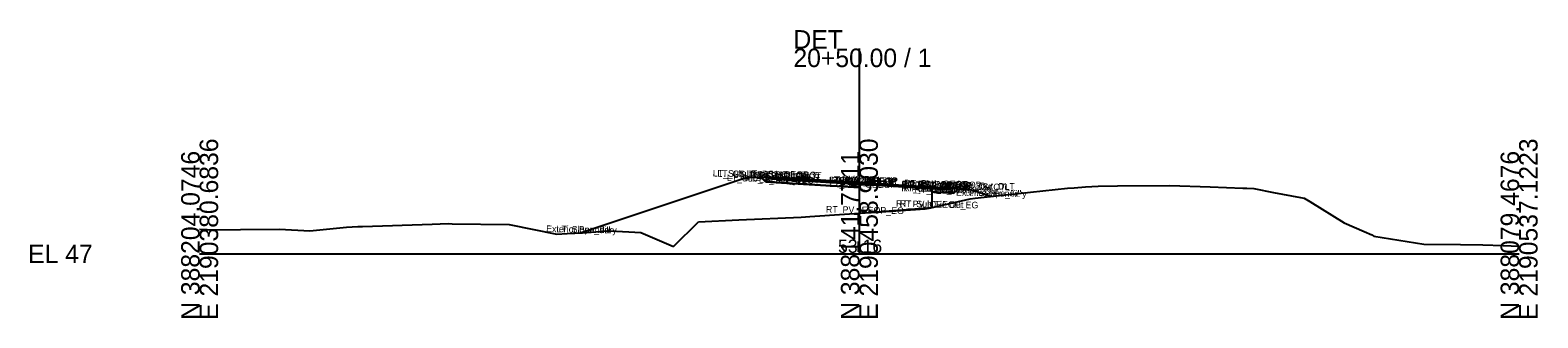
# Model space of a CAD drawing. Extents: x -26 to 1203, y -10 to 9543.
# Drawn here: x 974.3 to 1202.8, y 490.3 to 533.9 of the extents above; entities that cross this region are included whole.
import ezdxf

# ---------------------------------------------------------------- set-up
doc = ezdxf.new("R2010")
doc.units = 0
for name, color, linetype in [('Default', 7, 'Continuous'), ('Exist CMT Pavement', 7, 'Continuous'), ('Exist Cross Section Cell', 7, 'Continuous'), ('Exist XS Center Line Elevation Label', 7, 'Continuous'), ('Exist XS Ground Line', 7, 'Continuous'), ('Prop CMT Pvmt Course 1', 7, 'Continuous'), ('Prop CMT Pvmt Course 1 Wedge', 7, 'Continuous'), ('Prop CMT Pvmt Course 2', 7, 'Continuous'), ('Prop CMT Pvmt Course 2 Wedge', 7, 'Continuous'), ('Prop CMT Pvmt Course 3', 7, 'Continuous'), ('Prop CMT Pvmt Course 3 Wedge', 7, 'Continuous'), ('Prop CMT Pvmt Surface', 7, 'Continuous'), ('Prop CMT Pvmt Surface Shoulder', 7, 'Continuous'), ('Prop CMT Pvmt Wedge Surface 1', 7, 'Continuous'), ('Prop CMT Pvmt Wedge Surface 2', 7, 'Continuous'), ('Prop CMT Pvmt Wedge Surface 3', 7, 'Continuous'), ('Prop CMT Shld Paved Course 1', 7, 'Continuous'), ('Prop CMT Shld Paved Course 2', 7, 'Continuous'), ('Prop CMT Shld Paved Course 3', 7, 'Continuous'), ('Prop CMT Slope Grass', 7, 'Continuous'), ('Prop CMT Subgrade Earthwork', 7, 'Continuous'), ('Scratch_Level_0', 7, 'Continuous')]:
    doc.layers.add(name, color=color, linetype=linetype)

msp = doc.modelspace()

# ---------------------------------------------------------------- linework, layer by layer
at = {"layer": 'Exist CMT Pavement'}
msp.add_lwpolyline([(1100, 506.16), (1111, 507.03)], dxfattribs=at)
at = {"layer": 'Exist Cross Section Cell'}
for p, q in [((1100, 500), (1100, 531.1)), ((1000, 500), (1100, 500)), ((1100, 500), (1200, 500))]:
    msp.add_line(p, q, dxfattribs=at)
at = {"layer": 'Exist XS Ground Line'}
for p, q in [((1118.46, 508.56), (1131.53, 509.96)), ((1131.53, 509.96), (1132.56, 510.03)), ((1132.56, 510.03), (1134.28, 510.15)), ((1134.28, 510.15), (1136.17, 510.26)), ((1136.17, 510.26), (1139.1, 510.3)), ((1139.1, 510.3), (1147.08, 510.37)), ((1147.08, 510.37), (1153.17, 510.14)), ((1153.17, 510.14), (1158.12, 509.97)), ((1158.12, 509.97), (1158.74, 509.93)), ((1158.74, 509.93), (1159.77, 509.89)), ((1159.77, 509.89), (1162.75, 509.32)), ((1110.82, 506.99), (1116.8, 508.35)), ((1116.8, 508.35), (1117.57, 508.45)), ((1117.57, 508.45), (1118.46, 508.56)), ((1162.75, 509.32), (1166.86, 508.53)), ((1166.86, 508.53), (1167.43, 508.42)), ((1167.43, 508.42), (1168.26, 507.91)), ((1168.26, 507.91), (1173.5, 504.71)), ((1075.63, 504.87), (1081.71, 505.14)), ((1081.71, 505.14), (1091.17, 505.56)), ((1091.17, 505.56), (1092.49, 505.67)), ((1092.49, 505.67), (1097.76, 506.01)), ((1097.76, 506.01), (1100, 506.16)), ((1100, 506.16), (1101.77, 506.27)), ((1101.77, 506.27), (1109.97, 506.8)), ((1109.97, 506.8), (1110.82, 506.99)), ((1000, 503.73), (1002.36, 503.66)), ((1002.36, 503.66), (1006.19, 503.69)), ((1006.19, 503.69), (1012.1, 503.76)), ((1012.1, 503.76), (1016.71, 503.5)), ((1016.71, 503.5), (1022.24, 504.06)), ((1022.24, 504.06), (1023.99, 504.13)), ((1023.99, 504.13), (1024.68, 504.14)), ((1024.68, 504.14), (1035.22, 504.5)), ((1035.22, 504.5), (1037.67, 504.58)), ((1037.67, 504.58), (1038.29, 504.57)), ((1038.29, 504.57), (1046.89, 504.43)), ((1046.89, 504.43), (1054.13, 503.01)), ((1054.13, 503.01), (1055.73, 503.09)), ((1055.73, 503.09), (1058.02, 503.21)), ((1058.02, 503.21), (1061.92, 503.48)), ((1061.92, 503.48), (1062.25, 503.5)), ((1062.25, 503.5), (1066.89, 503.23)), ((1066.89, 503.23), (1071.83, 501.11)), ((1071.83, 501.11), (1075.63, 504.87)), ((1173.5, 504.71), (1176.53, 503.38)), ((1176.53, 503.38), (1177.66, 502.86)), ((1177.66, 502.86), (1177.96, 502.67)), ((1177.96, 502.67), (1185.56, 501.46)), ((1185.56, 501.46), (1191.1, 501.4)), ((1191.1, 501.4), (1194.52, 501.39)), ((1194.52, 501.39), (1197.59, 501.28)), ((1197.59, 501.28), (1200, 501.19))]:
    msp.add_line(p, q, dxfattribs=at)
at = {"layer": 'Prop CMT Pvmt Course 1'}
for points in [[(1100, 510.81), (1089, 511.47)], [(1089, 511.47), (1089, 511.22)], [(1089, 511.22), (1100, 510.56)], [(1100, 510.56), (1100, 510.81)], [(1100, 510.81), (1111, 510.15)], [(1100, 510.56), (1100, 510.81)], [(1111, 510.02), (1100, 510.68)], [(1100, 510.68), (1100, 510.56), (1100, 510.56)], [(1111, 510.15), (1111, 509.9), (1111, 509.9), (1111, 510.02)]]:
    msp.add_lwpolyline(points, dxfattribs=at)
msp.add_lwpolyline([(1100, 510.56), (1100, 510.68), (1100, 510.68), (1100, 510.56)], close=True, dxfattribs=at)
at = {"layer": 'Prop CMT Pvmt Course 1 Wedge'}
msp.add_lwpolyline([(1100, 510.68), (1111, 510.02)], dxfattribs=at)
at = {"layer": 'Prop CMT Pvmt Course 2'}
for points in [[(1089, 511.22), (1100, 510.56)], [(1100, 510.56), (1089, 511.22)], [(1089, 511.22), (1089, 511.22)], [(1100, 510.56), (1100, 510.56)], [(1111, 509.9), (1111, 509.9)]]:
    msp.add_lwpolyline(points, dxfattribs=at)
msp.add_lwpolyline([(1111, 509.9), (1111, 509.9), (1111, 509.9)], close=True, dxfattribs=at)
at = {"layer": 'Prop CMT Pvmt Course 2 Wedge'}
msp.add_lwpolyline([(1100, 510.56), (1111, 509.9)], dxfattribs=at)
at = {"layer": 'Prop CMT Pvmt Course 3'}
for points in [[(1100, 510.56), (1089, 511.22)], [(1089, 511.22), (1089, 510.72)], [(1089, 510.72), (1100, 510.06)], [(1100, 510.06), (1100, 510.56)], [(1111, 509.9), (1111, 509.9), (1111, 509.4), (1111, 509.4)], [(1111, 509.4), (1111, 509.9)]]:
    msp.add_lwpolyline(points, dxfattribs=at)
at = {"layer": 'Prop CMT Pvmt Course 3 Wedge'}
msp.add_lwpolyline([(1100, 510.56), (1111, 509.9)], dxfattribs=at)
at = {"layer": 'Prop CMT Pvmt Surface'}
for points in [[(1100, 510.81), (1089, 511.47)], [(1100, 510.81), (1111, 510.15)]]:
    msp.add_lwpolyline(points, dxfattribs=at)
at = {"layer": 'Prop CMT Pvmt Surface Shoulder'}
for points in [[(1089, 511.47), (1087, 511.59)], [(1111, 510.15), (1113, 510.03)]]:
    msp.add_lwpolyline(points, dxfattribs=at)
at = {"layer": 'Prop CMT Pvmt Wedge Surface 1'}
for points in [[(1100, 510.68), (1111, 510.02)], [(1111, 509.9), (1111, 510.15)], [(1111, 510.02), (1111, 509.9), (1111, 509.9)]]:
    msp.add_lwpolyline(points, dxfattribs=at)
at = {"layer": 'Prop CMT Pvmt Wedge Surface 2'}
for points in [[(1100, 510.56), (1111, 509.9)], [(1111, 509.9), (1111, 510.15)]]:
    msp.add_lwpolyline(points, dxfattribs=at)
at = {"layer": 'Prop CMT Pvmt Wedge Surface 3'}
for points in [[(1100, 510.56), (1111, 509.9)], [(1111, 509.9), (1111, 510.15)]]:
    msp.add_lwpolyline(points, dxfattribs=at)
at = {"layer": 'Prop CMT Shld Paved Course 1'}
for points in [[(1089, 511.47), (1087, 511.59), (1086.76, 511.35)], [(1086.76, 511.35), (1089, 511.22)], [(1089, 511.22), (1089, 511.47)], [(1111, 510.15), (1113, 510.03), (1113.27, 509.76)], [(1111, 509.9), (1111, 510.15)], [(1113.27, 509.76), (1111, 509.9)]]:
    msp.add_lwpolyline(points, dxfattribs=at)
at = {"layer": 'Prop CMT Shld Paved Course 2'}
for points in [[(1089, 511.22), (1086.76, 511.35)], [(1086.76, 511.35), (1086.76, 511.35)], [(1086.76, 511.35), (1089, 511.22)], [(1089, 511.22), (1089, 511.22)], [(1111, 509.9), (1113.27, 509.76)], [(1113.27, 509.76), (1111, 509.9)], [(1111, 509.9), (1111, 509.9)], [(1113.27, 509.76), (1113.27, 509.76)]]:
    msp.add_lwpolyline(points, dxfattribs=at)
at = {"layer": 'Prop CMT Shld Paved Course 3'}
for points in [[(1089, 511.22), (1086.76, 511.35), (1086.26, 511.38), (1085.79, 510.91)], [(1085.79, 510.91), (1089, 510.72)], [(1089, 510.72), (1089, 511.22)], [(1111, 509.9), (1113.27, 509.76), (1113.77, 509.73), (1114.3, 509.2)], [(1111, 509.4), (1111, 509.9)], [(1114.3, 509.2), (1111, 509.4)]]:
    msp.add_lwpolyline(points, dxfattribs=at)
at = {"layer": 'Prop CMT Slope Grass'}
for points in [[(1087, 511.59), (1083, 511.59), (1057.85, 503.2)], [(1113, 510.03), (1117, 509.71), (1119.97, 508.72)]]:
    msp.add_lwpolyline(points, dxfattribs=at)
at = {"layer": 'Prop CMT Subgrade Earthwork'}
for points in [[(1085.79, 510.91), (1085.11, 511.59)], [(1089, 510.72), (1085.79, 510.91)], [(1100, 510.06), (1089, 510.72)], [(1114.3, 509.2), (1114.97, 509.87)], [(1111, 509.4), (1111, 509.4)], [(1111, 509.4), (1111, 507.03)], [(1111, 509.4), (1114.3, 509.2)]]:
    msp.add_lwpolyline(points, dxfattribs=at)

# ---------------------------------------------------------------- texts
at = {"layer": 'Default'}
msp.add_text('-', height=0.0001, dxfattribs=at).set_placement((1000, 500))
at = {"layer": 'Exist Cross Section Cell'}
for s, p in [('DET', (1090, 531.1)), ('20+50.00 / 1', (1090, 528.3)), ('EL 47', (974, 498.6))]:
    msp.add_text(s, height=2.8, dxfattribs=at).set_placement(p)
for s, p in [('E 2190380.6836', (1002.8, 490)), ('E 2190458.9030', (1102.8, 490)), ('E 2190537.1223', (1202.8, 490)), ('N 388204.0746', (1000, 490)), ('N 388141.7711', (1100, 490)), ('N 388079.4676', (1200, 490))]:
    msp.add_text(s, height=2.8, rotation=90, dxfattribs=at).set_placement(p)
at = {"layer": 'Exist XS Center Line Elevation Label'}
msp.add_text('53.16', height=2, dxfattribs=at).set_placement((1096.76, 500.16))
at = {"layer": 'Scratch_Level_0'}
for s, p in [('LT_Sub_Trench_Out_DLT', (1077.77, 511.73)), ('LT_GS_OS_CTL', (1078.46, 511.68)), ('LT_Sub_Trench_Out', (1079.9, 511.03)), ('LT_PS3_Shelf_Out', (1080.92, 511.49)), ('LT_PS3_OEOP', (1082.55, 511.43)), ('LT_PS2_OEOP', (1082.55, 511.43)), ('LT_PS1_OEOP', (1082.91, 511.67)), ('LT_PV2_OEOT', (1084.75, 511.3)), ('LT_PV3_OEOT', (1084.75, 511.3)), ('LT_PV1_OEOT', (1084.87, 511.55)), ('LT_Sub_OEOT', (1084.77, 510.8)), ('LT_PV2_OEEOP', (1095.39, 510.65)), ('LT_PV3_OEEOP', (1095.39, 510.65)), ('LT_Sub_OEEOP', (1095.42, 510.15)), ('LT_PV1_OEEOP', (1095.51, 510.77)), ('RT_PV2_IEEOP', (1095.71, 510.64)), ('RT_PV3_IEEOP', (1095.71, 510.64)), ('LT_PV2_IEEOP', (1095.77, 510.64)), ('RT_PV1_IEEOP', (1095.83, 510.76)), ('LT_PV1_IEEOP', (1095.89, 510.76)), ('PV2_PGL', (1097.35, 510.61)), ('PV1_PGL', (1097.47, 510.86)), ('RT_PV2_OEEOP', (1106.33, 509.99)), ('RT_PV3_OEEOP', (1106.33, 509.99)), ('RT_Sub_OEEOP', (1106.36, 509.49)), ('RT_PV1_OEEOP', (1106.45, 510.11)), ('RT_PV3_OEOT', (1106.69, 509.98)), ('RT_PV2_OEOT', (1106.69, 509.98)), ('RT_Sub_OEOT', (1106.71, 509.48)), ('RT_PV1_OEOT', (1106.81, 510.23)), ('RT_Sub_Trench_Out_DLT', (1107.56, 510.02)), ('RT_Sub_Trench_Out', (1108.35, 509.32)), ('RT_PS3_Shelf_Out', (1108.37, 509.84)), ('RT_PS1_OEOP', (1108.85, 510.11)), ('RT_PS3_OEOP', (1108.99, 509.85)), ('RT_PS2_OEOP', (1108.99, 509.85)), ('RT_GS_OS_CTL', (1112.41, 509.8)), ('Exterior Boundary', (1114.64, 508.82)), ('RT_Slope_Fill', (1116.15, 508.79)), ('RT_PV_OEEOP_EG', (1105.54, 507.13)), ('RT_Sub Tie Out', (1106.1, 507.12)), ('RT_PV_IEEOP_EG', (1094.92, 506.26)), ('Exterior Boundary', (1052.51, 503.31)), ('LT_Slope_Fill', (1054.08, 503.28))]:
    msp.add_text(s, height=1, rotation=358.8836, dxfattribs=at).set_placement(p)

doc.saveas('drawing.dxf')
